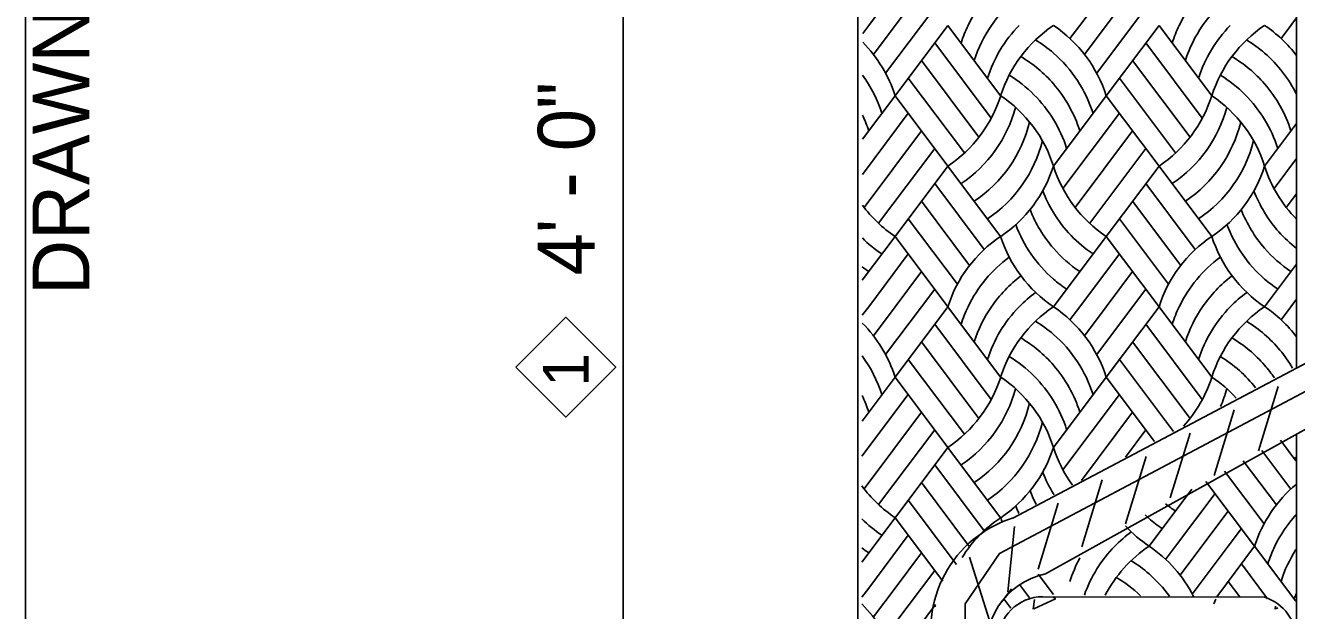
# Model space of a CAD drawing. Extents: x 99861 to 103151, y 100000 to 102076.
# Drawn here: x 99861 to 100218.6, y 101655.3 to 101820.1 of the extents above; entities that cross this region are included whole.
import ezdxf

# ---------------------------------------------------------------- set-up
doc = ezdxf.new("R2010")
doc.units = 0
for name, color, linetype in [('Level 1', 7, 'Continuous'), ('Level 15', 7, 'Continuous'), ('Level 2', 7, 'Continuous'), ('Level 20', 7, 'Continuous'), ('Level 4', 7, 'Continuous'), ('Level 6', 7, 'Continuous'), ('Level 62', 7, 'Continuous'), ('Level 8', 7, 'Continuous')]:
    doc.layers.add(name, color=color, linetype=linetype)

msp = doc.modelspace()

# ---------------------------------------------------------------- linework, layer by layer
at = {"layer": 'Level 1'}
msp.add_lwpolyline([(99861, 100000), (103150, 100000), (103150, 102076), (99861, 102076)], close=True, dxfattribs=at)
for points in [[(100321.78, 101778.52), (100290.24, 101761.47), (100138.82, 101681.37)], [(100300.06, 101750.32), (100147.93, 101665.64)]]:
    msp.add_lwpolyline(points, dxfattribs=at)
for centre, radius, start, end in [((100148.7, 101649.91), 33, 106.7676, 196.7676), ((100152.16, 101645.29), 20.78, 101.7334, 191.7334)]:
    msp.add_arc(centre, radius, start, end, dxfattribs=at)
at = {"layer": 'Level 15'}
msp.add_line((100029.13, 101974.77), (100029.13, 101575.23), dxfattribs=at)
at = {"layer": 'Level 2'}
for p, q in [((100095.13, 101575.23), (100095.13, 102062.01)), ((100218.59, 101723.57), (100218.59, 102034.68)), ((100218.59, 101582.05), (100218.59, 101705.01)), ((100147.24, 101659.24), (100147.19, 101659.23)), ((100209.6, 101659.07), (100147.24, 101659.24))]:
    msp.add_line(p, q, dxfattribs=at)
for centre, radius, start, end in [((100147.19, 101646.63), 12.6, 90, 180), ((100205.86, 101646.9), 12.73, 358.7615, 72.9174)]:
    msp.add_arc(centre, radius, start, end, dxfattribs=at)
at = {"layer": 'Level 20'}
msp.add_lwpolyline([(99998.98, 101723.85), (100013.02, 101737.89), (100027.07, 101723.85), (100013.02, 101709.8)], close=True, dxfattribs=at)
at = {"layer": 'Level 4'}
for p, q in [((100213.41, 101718.38), (100207.86, 101700.28)), ((100201.04, 101711.81), (100195.38, 101693.37)), ((100188.67, 101705.25), (100183.08, 101687.03)), ((100176.3, 101698.68), (100170.49, 101679.75)), ((100163.93, 101692.12), (100158.16, 101673.3)), ((100151.56, 101685.55), (100145.87, 101667.01)), ((100139.2, 101679.02), (100137.39, 101660.6)), ((100126.57, 101670.38), (100132.17, 101652.58))]:
    msp.add_line(p, q, dxfattribs=at)
msp.add_lwpolyline([(100681.92, 101961.48), (100134.98, 101671.41), (100125.32, 101657.21), (100124.78, 101580.54), (100138.68, 101563.02), (100211.51, 101562.94), (100231.08, 101580.8), (100297.11, 101749.23)], dxfattribs=at)
at = {"layer": 'Level 6'}
for p, q in [((100098.23, 101820.07), (100109.37, 101834.92)), ((100157.62, 101820.07), (100168.76, 101834.92)), ((100105.65, 101820.07), (100113.08, 101829.97)), ((100165.05, 101820.07), (100172.47, 101829.97)), ((100113.08, 101820.07), (100116.79, 101825.02)), ((100172.47, 101820.07), (100176.19, 101825.02)), ((100096.55, 101817.83), (100098.23, 101820.07)), ((100099.54, 101811.92), (100105.65, 101820.07)), ((100102.98, 101806.61), (100113.08, 101820.07)), ((100105.65, 101800.27), (100120.5, 101820.07)), ((100120.5, 101820.07), (100135.35, 101800.27)), ((100154.85, 101816.38), (100157.62, 101820.07)), ((100158.93, 101811.92), (100165.05, 101820.07)), ((100162.37, 101806.61), (100172.47, 101820.07)), ((100165.05, 101800.27), (100179.9, 101820.07)), ((100179.9, 101820.07), (100194.75, 101800.27)), ((100214.25, 101816.38), (100217.02, 101820.07)), ((100217.02, 101820.07), (100218.59, 101822.16)), ((100116.79, 101815.12), (100132.68, 101793.94)), ((100176.19, 101815.12), (100192.07, 101793.94)), ((100218.33, 101811.92), (100218.59, 101812.27)), ((100113.08, 101810.17), (100129.23, 101788.63)), ((100172.47, 101810.17), (100188.63, 101788.63)), ((100109.37, 101805.22), (100125.16, 101784.17)), ((100168.76, 101805.22), (100184.55, 101784.17)), ((100096.49, 101788.06), (100105.65, 101800.27)), ((100105.65, 101800.27), (100120.5, 101780.47)), ((100150.2, 101780.47), (100165.05, 101800.27)), ((100165.05, 101800.27), (100179.9, 101780.47)), ((100096.48, 101778.14), (100109.37, 101795.32)), ((100152.87, 101774.14), (100168.76, 101795.32)), ((100096.92, 101768.83), (100113.08, 101790.37)), ((100156.32, 101768.83), (100172.47, 101790.37)), ((100209.6, 101780.47), (100218.59, 101792.47)), ((100101, 101764.37), (100116.79, 101785.42)), ((100160.39, 101764.37), (100176.19, 101785.42)), ((100105.65, 101760.68), (100120.5, 101780.47)), ((100120.5, 101780.47), (100135.35, 101760.68)), ((100165.05, 101760.68), (100179.9, 101780.47)), ((100179.9, 101780.47), (100194.75, 101760.68)), ((100212.27, 101774.14), (100218.59, 101782.57)), ((100116.79, 101775.52), (100130.7, 101756.98)), ((100176.19, 101775.52), (100190.09, 101756.98)), ((100215.71, 101768.83), (100218.59, 101772.67)), ((100113.08, 101770.58), (100126.62, 101752.52)), ((100172.47, 101770.58), (100186.02, 101752.52)), ((100109.37, 101765.63), (100123.18, 101747.21)), ((100168.76, 101765.63), (100182.57, 101747.21)), ((100096.42, 101748.37), (100105.65, 101760.68)), ((100105.65, 101760.68), (100120.5, 101740.88)), ((100150.2, 101740.88), (100165.05, 101760.68)), ((100165.05, 101760.68), (100179.9, 101740.88)), ((100098.23, 101740.88), (100109.37, 101755.73)), ((100157.62, 101740.88), (100168.76, 101755.73)), ((100209.6, 101740.88), (100218.59, 101752.87)), ((100105.65, 101740.88), (100113.08, 101750.78)), ((100165.05, 101740.88), (100172.47, 101750.78)), ((100113.08, 101740.88), (100116.79, 101745.83)), ((100172.47, 101740.88), (100176.19, 101745.83)), ((100096.41, 101738.45), (100098.23, 101740.88)), ((100099.54, 101732.72), (100105.65, 101740.88)), ((100102.98, 101727.41), (100113.08, 101740.88)), ((100105.65, 101721.08), (100120.5, 101740.88)), ((100120.5, 101740.88), (100135.35, 101721.08)), ((100154.85, 101737.18), (100157.62, 101740.88)), ((100158.93, 101732.72), (100165.05, 101740.88)), ((100162.37, 101727.41), (100172.47, 101740.88)), ((100165.05, 101721.08), (100179.9, 101740.88)), ((100179.9, 101740.88), (100194.75, 101721.08)), ((100214.25, 101737.18), (100217.02, 101740.88)), ((100217.02, 101740.88), (100218.59, 101742.97)), ((100116.79, 101735.93), (100132.68, 101714.74)), ((100176.19, 101735.93), (100192.07, 101714.74)), ((100218.33, 101732.72), (100218.59, 101733.07)), ((100113.08, 101730.98), (100129.23, 101709.44)), ((100172.47, 101730.98), (100188.63, 101709.44)), ((100109.37, 101726.03), (100125.16, 101704.97)), ((100168.76, 101726.03), (100183.97, 101705.75)), ((100096.35, 101708.68), (100105.65, 101721.08)), ((100105.65, 101721.08), (100120.5, 101701.28)), ((100150.2, 101701.28), (100165.05, 101721.08)), ((100165.05, 101721.08), (100178.66, 101702.92)), ((100096.34, 101698.76), (100109.37, 101716.13)), ((100152.87, 101694.94), (100168.76, 101716.13)), ((100096.92, 101689.64), (100113.08, 101711.18)), ((100158.08, 101691.99), (100172.47, 101711.18)), ((100101, 101685.17), (100116.79, 101706.23)), ((100170.43, 101698.55), (100176.19, 101706.23)), ((100105.65, 101681.48), (100120.5, 101701.28)), ((100120.5, 101701.28), (100135.35, 101681.48)), ((100214.1, 101703.31), (100218.43, 101697.53)), ((100203.6, 101697.51), (100212.91, 101685.09)), ((100208.85, 101700.41), (100216.99, 101689.55)), ((100116.79, 101696.33), (100130.7, 101677.79)), ((100198.36, 101694.6), (100209.47, 101679.78)), ((100113.08, 101691.38), (100126.62, 101673.32)), ((100193.11, 101691.7), (100206.8, 101673.45)), ((100177.1, 101673.45), (100189.14, 101689.5)), ((100184.52, 101673.45), (100195.66, 101688.3)), ((100109.37, 101686.43), (100122.93, 101668.34)), ((100191.95, 101673.45), (100199.37, 101683.35)), ((100096.28, 101668.99), (100105.65, 101681.48)), ((100105.65, 101681.48), (100119.08, 101663.57)), ((100098.23, 101661.68), (100109.37, 101676.53)), ((100199.37, 101673.45), (100203.08, 101678.4)), ((100181.75, 101669.75), (100184.52, 101673.45)), ((100185.83, 101665.29), (100191.95, 101673.45)), ((100189.27, 101659.98), (100199.37, 101673.45)), ((100196.14, 101659.24), (100206.8, 101673.45)), ((100206.8, 101673.45), (100218.43, 101657.94)), ((100105.65, 101661.68), (100113.08, 101671.58)), ((100113.08, 101661.68), (100116.79, 101666.63)), ((100145.88, 101665.57), (100150.2, 101659.81)), ((100203.08, 101668.5), (100210.46, 101658.67)), ((100096.27, 101659.06), (100098.23, 101661.68)), ((100099.54, 101653.52), (100105.65, 101661.68)), ((100102.98, 101648.22), (100113.08, 101661.68)), ((100140.64, 101662.67), (100143.43, 101658.94)), ((100199.37, 101663.55), (100202.66, 101659.16)), ((100135.67, 101657.81), (100138.38, 101661.41)), ((100136.26, 101658.6), (100138.17, 101656.05)), ((100105.65, 101641.88), (100117.02, 101657.04)), ((100116.79, 101656.73), (100117.02, 101656.42))]:
    msp.add_line(p, q, dxfattribs=at)
for centre, start, end in [((100160.02, 101803.73), 126.3063, 154.2266), ((100219.42, 101803.73), 126.3063, 154.2266), ((100163.74, 101798.78), 127.1006, 145.4911), ((100223.13, 101798.78), 127.1006, 145.4911), ((100160.02, 101803.73), 154.2265, 162.3566), ((100163.74, 101798.78), 145.491, 162.3566), ((100167.45, 101793.83), 135.7127, 162.3566), ((100171.16, 101788.88), 123.9036, 162.3566), ((100129.24, 101788.88), 17.6434, 56.0963), ((100219.42, 101803.73), 154.2265, 162.3566), ((100223.13, 101798.78), 145.491, 162.3566), ((100226.85, 101793.83), 135.7127, 162.3566), ((100230.56, 101788.88), 123.9036, 162.3566), ((100188.64, 101788.88), 37.1429, 56.0963), ((100069.84, 101788.88), 17.6434, 44.7225), ((100125.53, 101783.93), 48.9597, 58.5465), ((100184.92, 101783.93), 48.9597, 58.5465), ((100125.53, 101783.93), 17.6434, 48.9597), ((100184.92, 101783.93), 26.3728, 48.9597), ((100121.82, 101778.98), 40.9413, 59.3021), ((100181.21, 101778.98), 40.9413, 59.3021), ((100066.13, 101783.93), 17.6434, 36.0139), ((100118.1, 101774.03), 31.3316, 58.4874), ((100177.5, 101774.03), 31.3316, 58.4874), ((100121.81, 101778.98), 17.6434, 40.9414), ((100181.21, 101778.98), 17.6434, 40.9414), ((100099.54, 101811.66), 303.9036, 342.3566), ((100114.39, 101769.09), 17.6434, 56.0964), ((100158.94, 101811.66), 303.9036, 342.3566), ((100173.79, 101769.09), 17.6434, 56.0964), ((100062.42, 101778.98), 17.6434, 24.8876), ((100103.25, 101806.71), 303.9036, 345.0113), ((100162.65, 101806.71), 303.9036, 345.0113), ((100106.97, 101801.76), 303.9036, 346.3199), ((100118.1, 101774.03), 17.6434, 31.3317), ((100166.36, 101801.76), 303.9036, 346.3199), ((100177.5, 101774.03), 17.6434, 31.3317), ((100110.68, 101796.81), 303.9036, 345.7713), ((100170.07, 101796.81), 303.9036, 345.7713), ((100114.39, 101791.86), 303.9036, 342.3566), ((100186.01, 101791.86), 197.6435, 236.0964), ((100173.79, 101791.86), 303.9036, 342.3566), ((100245.41, 101791.86), 197.6435, 224.4692), ((100182.3, 101786.91), 200.8778, 211.332), ((100241.69, 101786.91), 200.8778, 211.332), ((100126.61, 101791.86), 216.6397, 236.0964), ((100178.59, 101781.96), 201.4344, 220.9416), ((100182.3, 101786.91), 211.3319, 236.0964), ((100237.98, 101781.96), 201.4344, 220.9416), ((100241.69, 101786.91), 211.3319, 232.06), ((100174.87, 101777.01), 200.2432, 228.9599), ((100234.27, 101777.01), 200.2432, 228.9599), ((100122.9, 101786.91), 225.2472, 236.0964), ((100156.31, 101729.49), 123.9036, 162.3566), ((100171.16, 101772.07), 197.6434, 236.0964), ((100215.71, 101729.49), 123.9036, 162.3566), ((100230.56, 101772.07), 197.6434, 236.0964), ((100160.02, 101724.54), 126.3063, 154.2266), ((100178.58, 101781.96), 220.9415, 236.0964), ((100219.42, 101724.54), 126.3063, 154.2266), ((100237.98, 101781.96), 220.9415, 236.0964), ((100119.19, 101781.96), 232.7248, 236.0964), ((100163.74, 101719.59), 127.1006, 145.4911), ((100174.87, 101777.01), 228.9599, 236.0964), ((100223.13, 101719.59), 127.1006, 145.4911), ((100234.27, 101777.01), 228.9599, 236.0964), ((100167.45, 101714.64), 126.331, 135.7128), ((100226.85, 101714.64), 126.331, 135.7128), ((100160.02, 101724.54), 154.2265, 162.3566), ((100163.74, 101719.59), 145.491, 162.3566), ((100167.45, 101714.64), 135.7127, 162.3566), ((100171.16, 101709.69), 123.9036, 162.3566), ((100129.24, 101709.69), 17.6434, 56.0963), ((100219.42, 101724.54), 154.2265, 162.3566), ((100223.13, 101719.59), 145.491, 162.3566), ((100226.85, 101714.64), 135.7127, 162.3566), ((100230.56, 101709.69), 123.9036, 162.3566), ((100188.64, 101709.69), 37.1429, 56.0963), ((100125.53, 101704.74), 48.9597, 58.5465), ((100184.92, 101704.74), 48.9597, 58.5465), ((100069.84, 101709.69), 17.6434, 45.026), ((100125.53, 101704.74), 17.6434, 48.9597), ((100184.92, 101704.74), 30.0133, 48.9597), ((100121.82, 101699.79), 40.9413, 59.3021), ((100181.21, 101699.79), 40.9413, 59.3021), ((100066.13, 101704.74), 17.6434, 36.3762), ((100118.1, 101694.84), 31.3316, 58.4874), ((100177.5, 101694.84), 38.0851, 58.4874), ((100121.81, 101699.79), 17.6434, 40.9414), ((100181.21, 101699.79), 34.0337, 40.9414), ((100099.54, 101732.47), 303.9036, 342.3566), ((100114.39, 101689.89), 17.6434, 56.0964), ((100158.94, 101732.47), 317.8322, 342.3566), ((100173.79, 101689.89), 42.1876, 56.0964), ((100062.42, 101699.79), 17.6434, 25.3906), ((100103.25, 101727.52), 303.9036, 345.0113), ((100162.65, 101727.52), 336.9105, 345.0113), ((100106.97, 101722.57), 303.9036, 346.3199), ((100118.1, 101694.84), 17.6434, 31.3317), ((100110.68, 101717.62), 303.9036, 345.7713), ((100114.39, 101712.67), 303.9036, 342.3566), ((100186.01, 101712.67), 197.6435, 215.8682), ((100196.97, 101729.39), 303.9036, 304.824), ((100182.3, 101707.72), 200.8778, 211.332), ((100126.61, 101712.67), 216.2796, 236.0964), ((100242.61, 101662.06), 130.0405, 162.3566), ((100178.59, 101702.77), 201.4344, 207.8234), ((100182.3, 101707.72), 211.3319, 211.8366), ((100174.87, 101697.82), 200.2432, 203.8101), ((100205.48, 101714.54), 230.8142, 236.0964), ((100122.9, 101707.72), 224.945, 236.0964), ((100156.31, 101650.29), 123.9036, 147.8241), ((100171.16, 101692.87), 197.6434, 199.7762), ((100201.77, 101709.59), 226.7067, 228.9599), ((100201.77, 101709.59), 228.9599, 236.0964), ((100246.32, 101657.11), 137.9123, 154.2266), ((100194.35, 101647.21), 126.331, 135.7128), ((100198.06, 101704.64), 222.6923, 236.0964), ((100119.19, 101702.77), 232.4551, 236.0964), ((100194.35, 101647.21), 135.7127, 160.5803), ((100198.06, 101642.26), 123.9036, 152.466), ((100156.14, 101642.26), 27.0026, 56.0963), ((100246.32, 101657.11), 154.2265, 162.3566), ((100250.03, 101652.16), 147.2364, 162.3566), ((100190.64, 101652.16), 151.4269, 162.3566), ((100152.43, 101637.31), 48.9597, 58.5465), ((100152.43, 101637.31), 36.0156, 48.9597), ((100148.71, 101632.36), 46.2545, 59.3021), ((100253.74, 101647.21), 160.0015, 162.3566), ((100069.84, 101630.49), 17.6434, 45.3278)]:
    msp.add_arc(centre, 37.58, start, end, dxfattribs=at)
at = {"layer": 'Level 8'}
msp.add_line((100195.29, 101657.22), (100195.86, 101658.5), dxfattribs=at)
for points in [[(100144.52, 101655.75), (100144.89, 101658.44)], [(100150.14, 101659.23), (100150.73, 101658.62), (100144.65, 101655.8)], [(100212.58, 101655.75), (100212.69, 101656.55)], [(100213.36, 101656.1), (100212.71, 101655.8)]]:
    msp.add_lwpolyline(points, dxfattribs=at)

# ---------------------------------------------------------------- texts
at = {"layer": 'Level 20'}
for s, height, p in [('4\' - 0"', 16, (100021.13, 101749.66)), ('1', 12.8, (100019.42, 101718.35))]:
    msp.add_text(s, height=height, rotation=90, dxfattribs=at).set_placement(p)
at = {"layer": 'Level 62'}
msp.add_text('DRAWN BY:  FERN LIDDELL', height=16, rotation=90, dxfattribs=at).set_placement((99879, 101744.22))

doc.saveas('drawing.dxf')
